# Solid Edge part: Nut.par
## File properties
Author: Deepak Maini
Template: normal.par
Last saved by: Administrator
Revision: 3
Application: Solid Edge
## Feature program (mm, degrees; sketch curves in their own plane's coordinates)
sketch for "unnamed Protrusion 1" plane through (0, 0, 0) normal (0, 0, 1) x-axis (1, 0, 0)
  line (-7.5, 12.9904) -> (-15, 0)
  line (-15, 0) -> (-7.5, -12.9904)
  line (-7.5, -12.9904) -> (7.5, -12.9904)
  line (7.5, -12.9904) -> (15, 0)
  line (15, 0) -> (7.5, 12.9904)
  line (7.5, 12.9904) -> (-7.5, 12.9904)
extrude "unnamed Protrusion 1" add finite 12 symmetric
sketch for "unnamed RevolvedCutout 1" plane through (0, 0, 0) normal (0, -1, 0) x-axis (1, 0, 0)
  arc centre (10, 1) radius 5 from (10, 6) to (15, 1) cw
  line (15, 6) -> (15, 1)
  line (15, 6) -> (10, 6)
revolve "unnamed RevolvedCutout 1" cut full turn 360 deg
mirror "unnamed Mirror 1" of "unnamed RevolvedCutout 1" about plane through (0, 0, 0) normal (0, 0, 1)
revolve "unnamed RevolvedCutout 2" cut full turn 360 deg
sketch for "unnamed Hole 1" plane through (0, 0, 6) normal (0, 0, 1) x-axis (0, 1, 0)
  hole centre (0, 0) bore radius 6
hole "unnamed Hole 1" through
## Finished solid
Body 1: solid body, 11 faces, 22 edges, 12 vertices.
  Faces by surface: plane 8, torus 2, cylinder 1
  Edges by curve: intersection 12, line 6, circle 4
Bounding box of the edges (mm; curved faces can reach further): 30.000 x 25.981 x 12.000, from (-15, -12.9904, -6) to (15, 12.9904, 6).
Cylindrical faces by radius (mm): R6 x1
Toroidal faces (ring radius, tube radius in mm): R10 r5 x2
Planar faces by outward normal: +y 1, +z 1, -y 1, -z 1, oblique 4
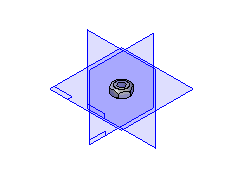
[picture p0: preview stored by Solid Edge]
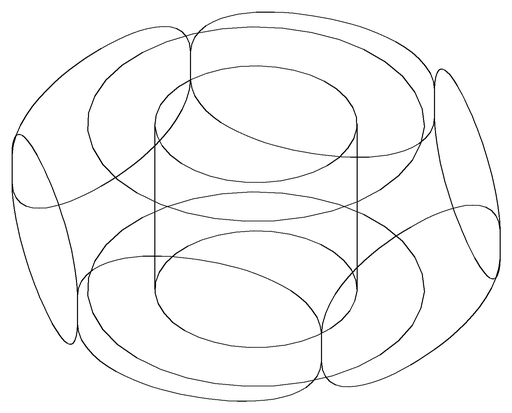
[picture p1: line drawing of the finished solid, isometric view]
